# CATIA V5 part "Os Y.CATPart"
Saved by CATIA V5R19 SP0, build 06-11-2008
Part number: Os Y
Bounding box of the stored display mesh (mm): x 0 to 700, y -52.033 to 2947.967, z -338.28 to 106.72
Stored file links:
  E:\Podręcznik\catia\Machine\Os Y.CATPart
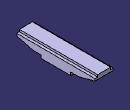
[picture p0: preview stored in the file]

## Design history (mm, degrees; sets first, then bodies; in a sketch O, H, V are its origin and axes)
Body1 (main body)
  Sketch1 on yz-plane, origin (0, 0, 0), H (0, 1, 0), V (0, 0, 1)
    line L1 (-52.0329, 26.7197) -> (2947.9671, 26.7197)
    line L2 (2947.9671, 26.7197) -> (2947.9671, -223.2803)
    line L3 (2947.9671, -223.2803) -> (-52.0329, -223.2803)
    line L4 (-52.0329, -223.2803) -> (-52.0329, 26.7197)
    length L1 = 3000
    length L4 = 250
    horizontal: L1 H, L3 H
    vertical: L2 V, L4 V
  Pad1: profile Sketch1, direction (1, 0, 0), length 700
  Sketch2 on end face of Pad1, origin (700, 0, 0), H (0, 1, 0), V (0, 0, 1)
    axis line L1 (1447.9671, 290.3935) -> (1447.9671, -507.332)
    reference projected line E1 (2947.9671, -323.2803) -> (2947.9671, 26.7197) from edge [face of Pad1 from Sketch1.L2 | end face of Pad1]
    line L2 (892.614, -223.2803) -> (2016.594, -223.2803)
    line L3 (2016.594, -223.2803) -> (2016.594, -338.2803)
    line L4 (2016.594, -338.2803) -> (892.614, -338.2803)
    line L5 (892.614, -338.2803) -> (892.614, -223.2803)
    reference projected line E2 (-52.0329, -223.2803) -> (2947.9671, -223.2803) from edge [face of Pad1 from Sketch1.L3 | end face of Pad1]
    distance L1 E1 = 1500
    length L4 = 1123.98
    length L3 = 115
    vertical: L1 V, L3 V, L5 V
    horizontal: L2 H, L4 H
    coincidence: L2 E2
  Pad2: profile Sketch2, direction (-1, 0, 0), length 700
  Sketch3 on face of Pad1 from Sketch1.L2, origin (0, 2947.9671, 0), H (-1, 0, 0), V (0, 0, 1)
    line L1 (-600, 106.7197) -> (-100, 106.7197)
    line L2 (-100, 106.7197) -> (-100, 26.7197)
    line L3 (-100, 26.7197) -> (-600, 26.7197)
    line L4 (-600, 26.7197) -> (-600, 106.7197)
    reference projected line E1 (0, 26.7197) -> (-700, 26.7197) from edge [face of Pad1 from Sketch1.L1 | face of Pad1 from Sketch1.L2]
    reference projected line E2 (0, -323.2803) -> (0, 26.7197) from edge [start face of Pad1 | face of Pad1 from Sketch1.L2]
    length L2 = 80
    length L1 = 500
    distance L2 E2 = 100
    horizontal: L1 H, L3 H
    vertical: L2 V, L4 V
    coincidence: E1 L3
  Pad3: profile Sketch3, direction (0, -1, 0), length 3000
  Sketch4 on face of Pad2, origin (700, 0, 0), H (0, 1, 0), V (0, 0, 1)
    axis line L1 (1447.9671, 323.6443) -> (1447.9671, -591.1028)
    reference projected line E1 (2947.9671, -323.2803) -> (2947.9671, 26.7197) from edge [face of Pad1 from Sketch1.L2 | end face of Pad1]
    point P3 (608.0002, -230.9899)
    point P4 (-115.9378, -37.7417)
    point P5 (-162.9975, -475.1025)
    point P6 (417.6812, -475.1025)
    line L2 (608.0002, -230.9899) -> (-115.9378, -37.7417)
    line L3 (-115.9378, -37.7417) -> (-162.9975, -475.1025)
    line L4 (-162.9975, -475.1025) -> (417.6812, -475.1025)
    line L5 (417.6812, -475.1025) -> (608.0002, -230.9899)
    point P7 (2895.9342, 0)
    point P8 (2287.934, -230.9899)
    point P9 (3011.8719, -37.7417)
    point P10 (3058.9316, -475.1025)
    point P11 (2478.2529, -475.1025)
    line L6 (2287.934, -230.9899) -> (3011.8719, -37.7417)
    line L7 (3011.8719, -37.7417) -> (3058.9316, -475.1025)
    line L8 (3058.9316, -475.1025) -> (2478.2529, -475.1025)
    line L9 (2478.2529, -475.1025) -> (2287.934, -230.9899)
    distance L1 E1 = 1500
    vertical: L1 V
    symmetry: O P7 L1, P3 P8 L1, P4 P9 L1, P5 P10 L1, P6 P11 L1, L2 L6 L1, L3 L7 L1, L4 L8 L1, L5 L9 L1
  Pocket1: profile Sketch4, direction (-1, 0, 0), through (limit type 6)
